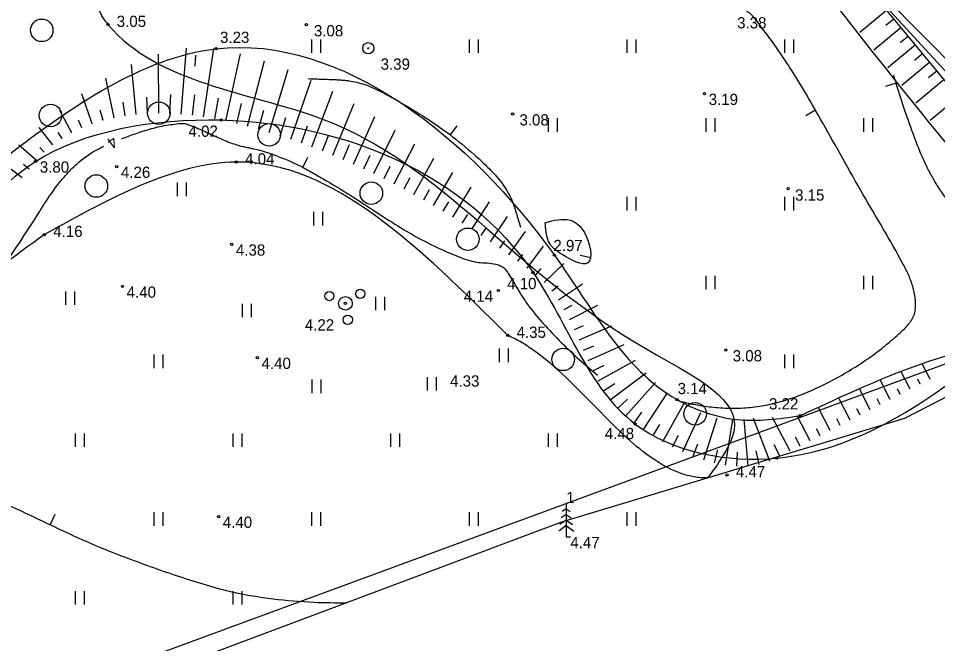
# Model space of a CAD drawing. Extents: x 519536 to 519949, y 326041 to 326519.
# Drawn here: x 519656.46 to 519697.28, y 326380.27 to 326408.03 of the extents above; entities that cross this region are included whole.
import ezdxf

# ---------------------------------------------------------------- set-up
doc = ezdxf.new("R2010")
doc.units = 0
for name, color, linetype in [('BUVE_ELEM_####_####_#', 7, 'Continuous'), ('NORB_ZOGS_KBST_####_#', 7, 'Continuous'), ('RAMI_UZMR_####_####_#', 7, 'Continuous'), ('RELJ_AATZ_####_TKST_#', 7, 'Continuous'), ('RELJ_ELEM_####_####_#', 7, 'Continuous'), ('RELJ_HORZ_####_TKST_#', 7, 'Continuous'), ('RELJ_HORZ_PAMT_####_#', 7, 'Continuous'), ('RELJ_HORZ_RESN_####_#', 7, 'Continuous'), ('RELJ_NOGA_####_####_#', 7, 'Continuous'), ('RELJ_NOGL_####_####_#', 7, 'Continuous'), ('ROBZ_UZMR_####_####_#', 7, 'Continuous'), ('TERT_DIAM_####_TKST_#', 7, 'Continuous'), ('TERT_ELEM_####_####_#', 7, 'Continuous'), ('TERT_KONT_####_####_#', 7, 'Continuous')]:
    doc.layers.add(name, color=color, linetype=linetype)

msp = doc.modelspace()

# ---------------------------------------------------------------- linework, layer by layer
at = {"layer": 'BUVE_ELEM_####_####_#'}
for radius in [0.25, 0.0225]:
    msp.add_circle((519672.002, 326406.707), radius, dxfattribs=at)
at = {"layer": 'NORB_ZOGS_KBST_####_#'}
msp.add_lwpolyline([(519704.591, 326396.84), (519691.702, 326412.425)], dxfattribs=at)
at = {"layer": 'RAMI_UZMR_####_####_#'}
msp.add_lwpolyline([(519606.503, 326354.123), (519598.183, 326371.842), (519589.598, 326374.981), (519581.568, 326396.559), (519571.96, 326403.209), (519550.477, 326420.838), (519546.03, 326425.168), (519546.311, 326425.748), (519562.267, 326424.735), (519567.537, 326424.176), (519622.695, 326420.6), (519656.101, 326418.428), (519678.291, 326416.771), (519682.862, 326421.74), (519706.678, 326395.86), (519695.81, 326390.264), (519680.586, 326385.663), (519636.229, 326369.014), (519636.521, 326358.648)], dxfattribs=at)
at = {"layer": 'RELJ_ELEM_####_####_#'}
for centre in [(519660.44, 326407.758), (519669.252, 326407.755), (519665.234, 326406.681), (519686.932, 326404.684), (519665.468, 326403.519), (519678.409, 326403.779), (519657.231, 326401.681), (519660.833, 326401.447), (519666.141, 326401.651), (519690.648, 326400.468), (519657.62, 326398.43), (519665.939, 326397.995), (519680.265, 326397.515), (519679.321, 326396.739), (519661.087, 326396.126), (519677.779, 326395.946), (519670.987, 326395.375), (519678.195, 326393.951), (519687.878, 326393.304), (519667.077, 326392.963), (519685.71, 326391.104), (519691.184, 326390.387), (519683.853, 326390.018), (519690.141, 326388.505), (519687.934, 326387.758), (519665.356, 326385.907)]:
    msp.add_circle(centre, 0.05, dxfattribs=at)
at = {"layer": 'RELJ_HORZ_PAMT_####_#'}
for p, q in [((519664.307, 326405.903), (519664.342, 326406.402)), ((519691.866, 326403.948), (519691.432, 326403.699)), ((519675.937, 326403.26), (519675.635, 326402.862)), ((519681.892, 326397.4), (519681.404, 326397.507)), ((519658.085, 326386.002), (519657.873, 326385.55))]:
    msp.add_line(p, q, dxfattribs=at)
for points in [[(519690.495, 326406.192), (519689.901, 326407.053), (519689.469, 326407.63), (519689.016, 326408.193), (519688.904, 326408.288), (519688.775, 326408.364), (519688.644, 326408.436), (519688.525, 326408.523), (519688.08, 326408.935), (519687.638, 326409.351), (519687.203, 326409.773), (519687.131, 326409.845)], [(519685.799, 326391.046), (519685.88, 326391.024), (519686.226, 326390.942), (519687.032, 326390.8), (519687.848, 326390.726), (519688.663, 326390.731), (519689.467, 326390.823), (519690.209, 326390.987), (519690.937, 326391.212), (519691.653, 326391.496), (519692.362, 326391.832), (519693.252, 326392.319), (519694.086, 326392.848), (519694.883, 326393.438), (519695.273, 326393.76), (519695.66, 326394.105), (519696.029, 326394.499), (519696.17, 326394.72), (519696.268, 326394.966), (519696.3, 326395.23), (519696.295, 326395.503), (519696.195, 326396.064), (519696, 326396.617), (519695.743, 326397.131), (519693.967, 326400.225), (519692.175, 326403.403), (519691.459, 326404.646), (519690.708, 326405.866), (519690.495, 326406.192)], [(519669.33, 326405.354), (519669.739, 326405.341), (519670.437, 326405.316), (519670.612, 326405.308), (519670.786, 326405.296), (519670.96, 326405.28), (519671.134, 326405.26), (519671.495, 326405.193), (519671.848, 326405.09)], [(519671.848, 326405.09), (519672.174, 326404.963), (519672.671, 326404.723), (519673.162, 326404.454), (519674.423, 326403.701), (519675.604, 326402.885), (519676.713, 326401.974), (519677.251, 326401.475), (519677.507, 326401.212), (519677.756, 326400.937), (519678.339, 326400.03), (519678.569, 326399.398), (519678.755, 326398.764)], [(519679.86, 326398.96), (519679.993, 326398.161), (519680.01, 326398.121), (519680.608, 326397.545), (519681.749, 326397.171), (519681.596, 326398.52), (519680.963, 326399.068), (519679.86, 326398.96)], [(519645.113, 326380.427), (519645.346, 326380.483), (519645.975, 326380.684), (519646.793, 326381.18), (519647.446, 326381.851), (519648.477, 326383.527), (519648.984, 326384.426), (519649.237, 326384.877), (519649.497, 326385.324), (519650.138, 326386.146), (519650.938, 326386.852), (519651.383, 326387.175), (519651.83, 326387.466), (519652.729, 326387.645), (519653.8, 326387.311), (519654.871, 326386.904), (519657.011, 326385.952), (519659.155, 326384.951), (519660.229, 326384.485), (519661.305, 326384.067), (519663.623, 326383.243), (519664.796, 326382.875), (519665.984, 326382.554), (519666.875, 326382.387), (519667.774, 326382.257), (519669.587, 326382.105), (519671.035, 326382.078)]]:
    msp.add_spline(points, degree=3, dxfattribs=at)
at = {"layer": 'RELJ_HORZ_RESN_####_#'}
for p, q in [((519695.443, 326405.154), (519694.966, 326405.006)), ((519669.092, 326401.416), (519669.316, 326401.863))]:
    msp.add_line(p, q, dxfattribs=at)
for points in [[(519696.193, 326402.912), (519695.782, 326404.076), (519695.435, 326405.179), (519695.334, 326405.503)], [(519661.045, 326402.684), (519661.663, 326402.911), (519662.29, 326403.111), (519663.028, 326403.285), (519663.399, 326403.337), (519663.77, 326403.367), (519663.859, 326403.357), (519664.03, 326403.303), (519664.196, 326403.244), (519664.519, 326403.111), (519665.158, 326402.819), (519665.797, 326402.541), (519666.459, 326402.334), (519666.665, 326402.291), (519666.842, 326402.258), (519668.003, 326401.9), (519669.111, 326401.407), (519669.646, 326401.106), (519670.178, 326400.799), (519671.226, 326400.164), (519671.314, 326400.108)], [(519698.726, 326392.928), (519698.835, 326392.956), (519699.387, 326393.081), (519700.212, 326393.312), (519700.348, 326393.365), (519700.482, 326393.424), (519700.553, 326393.541), (519700.577, 326393.647), (519700.598, 326393.752), (519700.618, 326393.858), (519700.643, 326393.962), (519700.652, 326393.992), (519700.893, 326394.479), (519700.969, 326394.602), (519701.051, 326394.72), (519701.134, 326394.839), (519701.212, 326394.964), (519701.379, 326395.301), (519701.436, 326395.476), (519701.469, 326395.653), (519701.452, 326395.76), (519701.411, 326395.865), (519701.356, 326395.96), (519701.296, 326396.052), (519701.16, 326396.221), (519700.831, 326396.549), (519700.475, 326396.868), (519700.14, 326397.197), (519698.898, 326398.547), (519698.295, 326399.242), (519698.001, 326399.597), (519697.714, 326399.959), (519697.09, 326400.915), (519696.951, 326401.164), (519696.818, 326401.415), (519696.58, 326401.93), (519696.193, 326402.912)], [(519651.586, 326391.007), (519651.731, 326391.16), (519652.424, 326392.002), (519653.05, 326392.903), (519653.654, 326393.816), (519655.537, 326396.623), (519657.398, 326399.442), (519657.707, 326399.931), (519658.325, 326400.782), (519658.673, 326401.181), (519659.052, 326401.564), (519659.888, 326402.162), (519660.254, 326402.351)], [(519671.314, 326400.108), (519673.308, 326398.821), (519674.373, 326398.203), (519675.474, 326397.669), (519675.632, 326397.599)], [(519675.632, 326397.599), (519676.511, 326397.276), (519676.89, 326397.197), (519677.285, 326397.168), (519677.671, 326397.11), (519677.853, 326397.046), (519678.025, 326396.947), (519678.219, 326396.697), (519678.416, 326396.382), (519678.603, 326396.061), (519678.794, 326395.743), (519679.001, 326395.435), (519679.755, 326394.498), (519680.584, 326393.624), (519681.367, 326392.881), (519682.187, 326392.183)]]:
    msp.add_spline(points, degree=3, dxfattribs=at)
at = {"layer": 'RELJ_NOGA_####_####_#'}
for p, q in [((519695.031, 326408.399), (519693.822, 326407.399)), ((519695.35, 326408.014), (519694.985, 326407.712)), ((519695.669, 326407.629), (519694.446, 326406.617)), ((519695.987, 326407.243), (519695.618, 326406.938)), ((519696.306, 326406.858), (519695.069, 326405.835)), ((519662.697, 326403.817), (519662.687, 326406.446)), ((519663.695, 326403.778), (519663.927, 326406.705)), ((519664.688, 326403.662), (519665.148, 326406.693)), ((519665.671, 326403.475), (519666.328, 326406.46)), ((519696.625, 326406.473), (519696.252, 326406.164)), ((519661.698, 326403.769), (519661.489, 326405.98)), ((519666.642, 326403.24), (519667.399, 326406.145)), ((519696.943, 326406.087), (519695.693, 326405.054)), ((519667.605, 326402.968), (519668.438, 326405.754)), ((519697.262, 326405.702), (519696.885, 326405.39)), ((519660.71, 326403.62), (519660.348, 326405.37)), ((519668.557, 326402.663), (519669.459, 326405.292)), ((519697.581, 326405.317), (519696.319, 326404.273)), ((519669.498, 326402.326), (519670.427, 326404.792)), ((519659.747, 326403.353), (519659.284, 326404.677)), ((519661.202, 326403.708), (519661.115, 326404.303)), ((519662.197, 326403.805), (519662.161, 326404.533)), ((519663.196, 326403.808), (519663.229, 326404.647)), ((519664.193, 326403.729), (519664.299, 326404.631)), ((519665.181, 326403.577), (519665.351, 326404.481)), ((519698.218, 326404.546), (519696.946, 326403.494)), ((519658.831, 326402.953), (519658.299, 326403.943)), ((519660.224, 326403.502), (519660.1, 326403.962)), ((519666.158, 326403.362), (519666.373, 326404.247)), ((519667.125, 326403.108), (519667.367, 326403.962)), ((519670.428, 326401.958), (519671.373, 326404.248)), ((519659.281, 326403.171), (519659.133, 326403.515)), ((519660.224, 326403.502), (519660.224, 326403.502)), ((519660.71, 326403.62), (519660.71, 326403.621)), ((519661.202, 326403.708), (519661.202, 326403.708)), ((519661.698, 326403.769), (519661.698, 326403.77)), ((519662.197, 326403.805), (519662.197, 326403.805)), ((519662.697, 326403.817), (519662.697, 326403.818)), ((519663.196, 326403.808), (519663.196, 326403.808)), ((519663.695, 326403.778), (519663.696, 326403.779)), ((519664.193, 326403.729), (519664.193, 326403.73)), ((519664.688, 326403.662), (519664.689, 326403.663)), ((519665.181, 326403.577), (519665.181, 326403.577)), ((519665.671, 326403.475), (519665.671, 326403.476)), ((519668.082, 326402.82), (519668.344, 326403.633)), ((519671.346, 326401.562), (519672.296, 326403.671)), ((519657.994, 326402.409), (519657.381, 326403.189)), ((519659.281, 326403.171), (519659.281, 326403.171)), ((519659.747, 326403.353), (519659.746, 326403.354)), ((519666.158, 326403.362), (519666.158, 326403.362)), ((519666.642, 326403.24), (519666.643, 326403.241)), ((519667.125, 326403.108), (519667.125, 326403.109)), ((519669.029, 326402.498), (519669.302, 326403.264)), ((519672.252, 326401.138), (519673.188, 326403.074)), ((519658.401, 326402.699), (519658.23, 326402.96)), ((519658.401, 326402.699), (519658.401, 326402.699)), ((519658.831, 326402.953), (519658.831, 326402.954)), ((519667.605, 326402.968), (519667.605, 326402.969)), ((519668.082, 326402.82), (519668.082, 326402.82)), ((519668.557, 326402.663), (519668.557, 326402.664)), ((519669.965, 326402.146), (519670.247, 326402.859)), ((519657.268, 326401.723), (519656.49, 326402.403)), ((519657.615, 326402.083), (519657.41, 326402.298)), ((519657.994, 326402.409), (519657.993, 326402.409)), ((519669.029, 326402.498), (519669.029, 326402.499)), ((519669.498, 326402.326), (519669.499, 326402.327)), ((519670.889, 326401.763), (519671.172, 326402.424)), ((519673.146, 326400.69), (519674.062, 326402.455)), ((519657.615, 326402.083), (519657.615, 326402.083)), ((519669.965, 326402.146), (519669.965, 326402.146)), ((519670.428, 326401.958), (519670.429, 326401.959)), ((519671.801, 326401.353), (519672.085, 326401.959)), ((519674.027, 326400.217), (519674.918, 326401.823)), ((519656.636, 326400.948), (519655.698, 326401.664)), ((519656.946, 326401.341), (519656.689, 326401.549)), ((519657.268, 326401.723), (519657.267, 326401.724)), ((519670.889, 326401.763), (519670.889, 326401.764)), ((519671.346, 326401.562), (519671.347, 326401.563)), ((519672.701, 326400.917), (519672.979, 326401.472)), ((519656.946, 326401.341), (519656.945, 326401.341)), ((519671.801, 326401.353), (519671.801, 326401.354)), ((519672.252, 326401.138), (519672.253, 326401.139)), ((519674.896, 326399.722), (519675.752, 326401.184)), ((519656.636, 326400.948), (519656.635, 326400.949)), ((519672.701, 326400.917), (519672.701, 326400.917)), ((519673.146, 326400.69), (519673.146, 326400.691)), ((519673.588, 326400.456), (519673.858, 326400.962)), ((519673.588, 326400.456), (519673.588, 326400.457)), ((519674.027, 326400.217), (519674.028, 326400.218)), ((519674.463, 326399.972), (519674.725, 326400.433)), ((519675.752, 326399.205), (519676.577, 326400.535)), ((519674.463, 326399.972), (519674.463, 326399.972)), ((519675.326, 326399.466), (519675.577, 326399.885)), ((519676.595, 326398.668), (519677.39, 326399.882)), ((519674.896, 326399.722), (519674.896, 326399.723)), ((519675.326, 326399.466), (519675.326, 326399.466)), ((519675.752, 326399.205), (519675.752, 326399.206)), ((519676.175, 326398.939), (519676.419, 326399.319)), ((519677.426, 326398.111), (519678.19, 326399.228)), ((519676.175, 326398.939), (519676.175, 326398.939)), ((519676.595, 326398.668), (519676.596, 326398.668)), ((519677.012, 326398.392), (519677.246, 326398.741)), ((519678.244, 326397.536), (519678.989, 326398.57)), ((519677.012, 326398.392), (519677.013, 326398.392)), ((519677.837, 326397.826), (519678.062, 326398.148)), ((519677.426, 326398.111), (519677.427, 326398.112)), ((519677.837, 326397.826), (519677.837, 326397.826)), ((519679.05, 326396.944), (519679.78, 326397.916)), ((519678.244, 326397.536), (519678.245, 326397.537)), ((519678.649, 326397.242), (519678.869, 326397.543)), ((519678.649, 326397.242), (519678.649, 326397.243)), ((519679.05, 326396.944), (519679.051, 326396.945)), ((519679.815, 326396.302), (519680.679, 326397.147)), ((519679.447, 326396.639), (519679.675, 326396.917)), ((519679.447, 326396.639), (519679.447, 326396.64)), ((519679.815, 326396.302), (519679.816, 326396.303)), ((519680.147, 326395.928), (519680.437, 326396.159)), ((519680.442, 326395.525), (519681.512, 326396.237)), ((519680.147, 326395.928), (519680.147, 326395.928)), ((519680.442, 326395.525), (519680.443, 326395.525)), ((519680.705, 326395.099), (519681.055, 326395.3)), ((519680.942, 326394.659), (519682.201, 326395.302)), ((519680.705, 326395.099), (519680.705, 326395.1)), ((519680.942, 326394.659), (519680.943, 326394.66)), ((519681.159, 326394.209), (519681.564, 326394.398)), ((519681.159, 326394.209), (519681.159, 326394.209)), ((519681.364, 326393.753), (519682.809, 326394.385)), ((519681.364, 326393.753), (519681.365, 326393.753)), ((519681.564, 326393.294), (519682.021, 326393.494)), ((519681.564, 326393.294), (519681.564, 326393.295)), ((519681.766, 326392.837), (519683.362, 326393.554)), ((519682.207, 326391.94), (519683.874, 326392.851)), ((519681.766, 326392.837), (519681.767, 326392.838)), ((519681.978, 326392.384), (519682.472, 326392.624)), ((519696.955, 326392.016), (519696.604, 326392.696)), ((519681.978, 326392.384), (519681.978, 326392.385)), ((519682.743, 326391.097), (519684.34, 326392.295)), ((519696.066, 326391.558), (519695.666, 326392.334)), ((519682.207, 326391.94), (519682.208, 326391.941)), ((519682.46, 326391.509), (519682.956, 326391.822)), ((519683.417, 326390.36), (519684.756, 326391.866)), ((519695.177, 326391.1), (519694.74, 326391.948)), ((519696.51, 326391.787), (519696.397, 326392.006)), ((519696.51, 326391.787), (519696.51, 326391.787)), ((519696.955, 326392.016), (519696.954, 326392.017)), ((519682.46, 326391.509), (519682.46, 326391.509)), ((519684.223, 326389.769), (519685.289, 326391.406)), ((519694.288, 326390.642), (519693.822, 326391.547)), ((519695.622, 326391.329), (519695.496, 326391.573)), ((519695.622, 326391.329), (519695.621, 326391.329)), ((519696.066, 326391.558), (519696.066, 326391.559)), ((519682.743, 326391.097), (519682.744, 326391.098)), ((519683.062, 326390.712), (519683.511, 326391.116)), ((519685.076, 326389.248), (519686.014, 326390.912)), ((519693.399, 326390.184), (519692.906, 326391.14)), ((519694.733, 326390.871), (519694.597, 326391.134)), ((519694.733, 326390.871), (519694.732, 326390.871)), ((519695.177, 326391.1), (519695.177, 326391.101)), ((519683.062, 326390.712), (519683.062, 326390.712)), ((519683.808, 326390.049), (519684.152, 326390.54)), ((519685.965, 326388.792), (519686.761, 326390.528)), ((519692.51, 326389.726), (519691.991, 326390.734)), ((519693.844, 326390.413), (519693.7, 326390.692)), ((519693.844, 326390.413), (519693.843, 326390.413)), ((519694.288, 326390.642), (519694.288, 326390.643)), ((519683.417, 326390.36), (519683.418, 326390.361)), ((519683.808, 326390.049), (519683.808, 326390.05)), ((519684.645, 326389.502), (519684.945, 326389.996)), ((519686.896, 326388.427), (519687.493, 326390.291)), ((519687.867, 326388.192), (519688.182, 326390.214)), ((519688.864, 326388.15), (519688.693, 326390.238)), ((519689.836, 326388.367), (519689.113, 326390.263)), ((519690.732, 326388.81), (519689.957, 326390.314)), ((519691.621, 326389.268), (519691.049, 326390.379)), ((519692.955, 326389.955), (519692.803, 326390.249)), ((519693.399, 326390.184), (519693.399, 326390.185)), ((519684.223, 326389.769), (519684.223, 326389.77)), ((519692.066, 326389.497), (519691.905, 326389.808)), ((519692.51, 326389.726), (519692.51, 326389.727)), ((519692.955, 326389.955), (519692.955, 326389.955)), ((519684.645, 326389.502), (519684.645, 326389.502)), ((519685.076, 326389.248), (519685.076, 326389.249)), ((519685.516, 326389.011), (519685.776, 326389.52)), ((519691.177, 326389.039), (519690.975, 326389.431)), ((519691.621, 326389.268), (519691.621, 326389.269)), ((519692.066, 326389.497), (519692.066, 326389.497)), ((519685.516, 326389.011), (519685.516, 326389.011)), ((519685.965, 326388.792), (519685.966, 326388.793)), ((519686.425, 326388.596), (519686.639, 326389.134)), ((519687.376, 326388.29), (519687.522, 326388.872)), ((519688.364, 326388.143), (519688.39, 326388.767)), ((519689.358, 326388.223), (519689.227, 326388.831)), ((519690.288, 326388.581), (519690.025, 326389.091)), ((519690.732, 326388.81), (519690.732, 326388.811)), ((519691.177, 326389.039), (519691.177, 326389.039)), ((519686.425, 326388.596), (519686.425, 326388.596)), ((519686.896, 326388.427), (519686.896, 326388.428)), ((519689.836, 326388.367), (519689.836, 326388.368)), ((519690.288, 326388.581), (519690.288, 326388.581)), ((519687.376, 326388.29), (519687.377, 326388.29)), ((519687.867, 326388.192), (519687.867, 326388.193)), ((519688.364, 326388.143), (519688.364, 326388.143)), ((519688.864, 326388.15), (519688.864, 326388.151)), ((519689.358, 326388.223), (519689.358, 326388.223))]:
    msp.add_line(p, q, dxfattribs=at)
msp.add_spline([(519633.005, 326382.956), (519639.907, 326381.113), (519643.418, 326377.883), (519651.003, 326389.626), (519657.231, 326401.681), (519665.468, 326403.519), (519679.321, 326396.739), (519683.853, 326390.018), (519690.141, 326388.505), (519700.416, 326393.799)], degree=3, dxfattribs=at)
at = {"layer": 'RELJ_NOGL_####_####_#'}
for points in [[(519690.926, 326411.003), (519701.164, 326398.42), (519703.254, 326396.147)], [(519639.78, 326385.057), (519642.535, 326381.732), (519643.997, 326380.646), (519647.881, 326390.255), (519656.007, 326401.958), (519665.234, 326406.681), (519680.265, 326397.515), (519685.71, 326391.104), (519688.362, 326390.219), (519691.184, 326390.387)], [(519691.184, 326390.387), (519696.984, 326392.832), (519700.416, 326393.799)]]:
    msp.add_spline(points, degree=3, dxfattribs=at)
at = {"layer": 'ROBZ_UZMR_####_####_#'}
for p, q in [((519700.236, 326403.605), (519683.072, 326421.021)), ((519634.774, 326369.546), (519706.067, 326395.801))]:
    msp.add_line(p, q, dxfattribs=at)
at = {"layer": 'TERT_ELEM_####_####_#'}
for p, q in [((519669.5, 326406.5), (519669.5, 326407.1)), ((519669.9, 326406.5), (519669.9, 326407.1)), ((519676.5, 326406.5), (519676.5, 326407.1)), ((519676.9, 326406.5), (519676.9, 326407.1)), ((519683.5, 326406.5), (519683.5, 326407.1)), ((519683.9, 326406.5), (519683.9, 326407.1)), ((519690.5, 326406.5), (519690.5, 326407.1)), ((519690.9, 326406.5), (519690.9, 326407.1)), ((519680, 326403), (519680, 326403.6)), ((519680.4, 326403), (519680.4, 326403.6)), ((519687, 326403), (519687, 326403.6)), ((519687.4, 326403), (519687.4, 326403.6)), ((519694, 326403), (519694, 326403.6)), ((519694.4, 326403), (519694.4, 326403.6)), ((519663.528, 326400.139), (519663.528, 326400.739)), ((519663.928, 326400.139), (519663.928, 326400.739)), ((519683.5, 326399.5), (519683.5, 326400.1)), ((519683.9, 326399.5), (519683.9, 326400.1)), ((519690.5, 326399.5), (519690.5, 326400.1)), ((519690.9, 326399.5), (519690.9, 326400.1)), ((519669.589, 326398.84), (519669.589, 326399.44)), ((519669.989, 326398.84), (519669.989, 326399.44)), ((519687, 326396), (519687, 326396.6)), ((519687.4, 326396), (519687.4, 326396.6)), ((519694, 326396), (519694, 326396.6)), ((519694.4, 326396), (519694.4, 326396.6)), ((519658.57, 326395.303), (519658.57, 326395.903)), ((519658.97, 326395.303), (519658.97, 326395.903)), ((519666.414, 326394.757), (519666.414, 326395.357)), ((519666.814, 326394.757), (519666.814, 326395.357)), ((519672.333, 326395.066), (519672.333, 326395.666)), ((519672.733, 326395.066), (519672.733, 326395.666)), ((519677.821, 326392.766), (519677.821, 326393.366)), ((519678.221, 326392.766), (519678.221, 326393.366)), ((519662.5, 326392.5), (519662.5, 326393.1)), ((519662.9, 326392.5), (519662.9, 326393.1)), ((519690.5, 326392.5), (519690.5, 326393.1)), ((519690.9, 326392.5), (519690.9, 326393.1)), ((519674.632, 326391.501), (519674.632, 326392.101)), ((519675.032, 326391.501), (519675.032, 326392.101)), ((519669.503, 326391.393), (519669.503, 326391.993)), ((519669.903, 326391.393), (519669.903, 326391.993)), ((519659, 326389), (519659, 326389.6)), ((519659.4, 326389), (519659.4, 326389.6)), ((519666, 326389), (519666, 326389.6)), ((519666.4, 326389), (519666.4, 326389.6)), ((519673, 326389), (519673, 326389.6)), ((519673.4, 326389), (519673.4, 326389.6)), ((519680, 326389), (519680, 326389.6)), ((519680.4, 326389), (519680.4, 326389.6)), ((519680.788, 326386.504), (519680.788, 326385.004)), ((519662.5, 326385.5), (519662.5, 326386.1)), ((519662.9, 326385.5), (519662.9, 326386.1)), ((519669.5, 326385.5), (519669.5, 326386.1)), ((519669.9, 326385.5), (519669.9, 326386.1)), ((519676.5, 326385.5), (519676.5, 326386.1)), ((519676.9, 326385.5), (519676.9, 326386.1)), ((519680.788, 326386.004), (519680.572, 326385.846)), ((519680.788, 326386.254), (519680.612, 326386.126)), ((519680.788, 326386.254), (519680.962, 326386.126)), ((519680.788, 326386.004), (519681.004, 326385.846)), ((519683.5, 326385.5), (519683.5, 326386.1)), ((519683.9, 326385.5), (519683.9, 326386.1)), ((519680.788, 326385.504), (519680.456, 326385.26)), ((519680.788, 326385.754), (519680.51, 326385.55)), ((519680.788, 326385.754), (519681.066, 326385.55)), ((519680.788, 326385.504), (519681.122, 326385.26)), ((519680.788, 326385.004), (519680.988, 326385.004)), ((519659, 326382), (519659, 326382.6)), ((519659.4, 326382), (519659.4, 326382.6)), ((519666, 326382), (519666, 326382.6)), ((519666.4, 326382), (519666.4, 326382.6))]:
    msp.add_line(p, q, dxfattribs=at)
for centre, radius in [((519657.5, 326407.5), 0.5), ((519662.697, 326403.817), 0.5), ((519657.893, 326403.721), 0.5), ((519667.598, 326402.859), 0.5), ((519659.926, 326400.587), 0.5), ((519672.138, 326400.271), 0.5), ((519676.426, 326398.222), 0.5), ((519670.273, 326395.699), 0.204), ((519671.648, 326395.8), 0.207), ((519670.987, 326395.375), 0.301), ((519671.09, 326394.647), 0.205), ((519680.657, 326392.888), 0.5), ((519686.518, 326390.473), 0.5)]:
    msp.add_circle(centre, radius, dxfattribs=at)
at = {"layer": 'TERT_KONT_####_####_#'}
for points in [[(519656.276, 326418.415), (519657.694, 326417.286), (519658.907, 326416.161), (519659.485, 326415.554), (519660.042, 326414.916), (519660.292, 326414.538), (519660.452, 326414.128), (519660.507, 326413.905), (519660.548, 326413.68), (519660.55, 326413.232), (519660.23, 326411.271), (519659.915, 326409.343), (519659.92, 326408.916), (519659.963, 326408.702), (519660.02, 326408.488), (519660.089, 326408.29), (519660.184, 326408.105), (519660.44, 326407.758), (519669.963, 326403.559), (519684.467, 326393.28), (519688.263, 326389.935), (519687.074, 326387.624)], [(519678.195, 326393.951), (519666.141, 326401.651), (519657.62, 326398.43)], [(519657.62, 326398.43), (519650.463, 326391.501), (519643.964, 326376.852), (519640.6, 326375.326)], [(519687.074, 326387.624), (519686.772, 326387.633), (519686.475, 326387.67), (519685.892, 326387.821), (519684.769, 326388.39), (519682.621, 326390.239), (519680.48, 326392.362), (519679.365, 326393.274), (519678.788, 326393.648), (519678.494, 326393.809), (519678.195, 326393.951)]]:
    msp.add_spline(points, degree=3, dxfattribs=at)

# ---------------------------------------------------------------- texts
at = {"layer": 'RELJ_AATZ_####_TKST_#'}
for s, p in [('3.05', (519660.833, 326407.651)), (' 3.38', (519688.195, 326407.585)), ('3.08', (519669.588, 326407.233)), (' 3.23', (519665.234, 326406.94)), ('3.39', (519672.55, 326405.75)), (' 3.19', (519686.932, 326404.184)), ('3.08', (519678.715, 326403.274)), (' 4.02', (519663.834, 326402.773)), ('4.04', (519666.534, 326401.543)), (' 3.80', (519657.231, 326401.181)), (' 4.26', (519660.833, 326400.947)), ('3.15', (519690.954, 326399.937)), ('4.16', (519658.013, 326398.323)), (' 2.97', (519680.036, 326397.695)), (' 4.38', (519665.939, 326397.495)), (' 4.40', (519661.087, 326395.626)), (' 4.10', (519677.983, 326396.003)), (' 4.14', (519676.057, 326395.446)), ('4.22', (519669.185, 326394.17)), ('4.35', (519678.588, 326393.844)), ('3.08', (519688.184, 326392.797)), (' 4.40', (519667.077, 326392.463)), (' 4.33', (519675.449, 326391.679)), (' 3.14', (519685.551, 326391.344)), (' 3.22', (519689.61, 326390.664)), (' 4.48', (519682.317, 326389.345)), ('4.47', (519688.327, 326387.65)), (' 4.40', (519665.356, 326385.407)), (' 4.47', (519680.788, 326384.504))]:
    msp.add_text(s, height=0.5, dxfattribs=at).set_placement(p)
at = {"layer": 'RELJ_HORZ_####_TKST_#'}
msp.add_text('4', height=0.5, rotation=215.3228, dxfattribs=at).set_placement((519660.647, 326402.834))
at = {"layer": 'TERT_DIAM_####_TKST_#'}
msp.add_text('1', height=0.5, dxfattribs=at).set_placement((519680.788, 326386.504))

doc.saveas('drawing.dxf')
